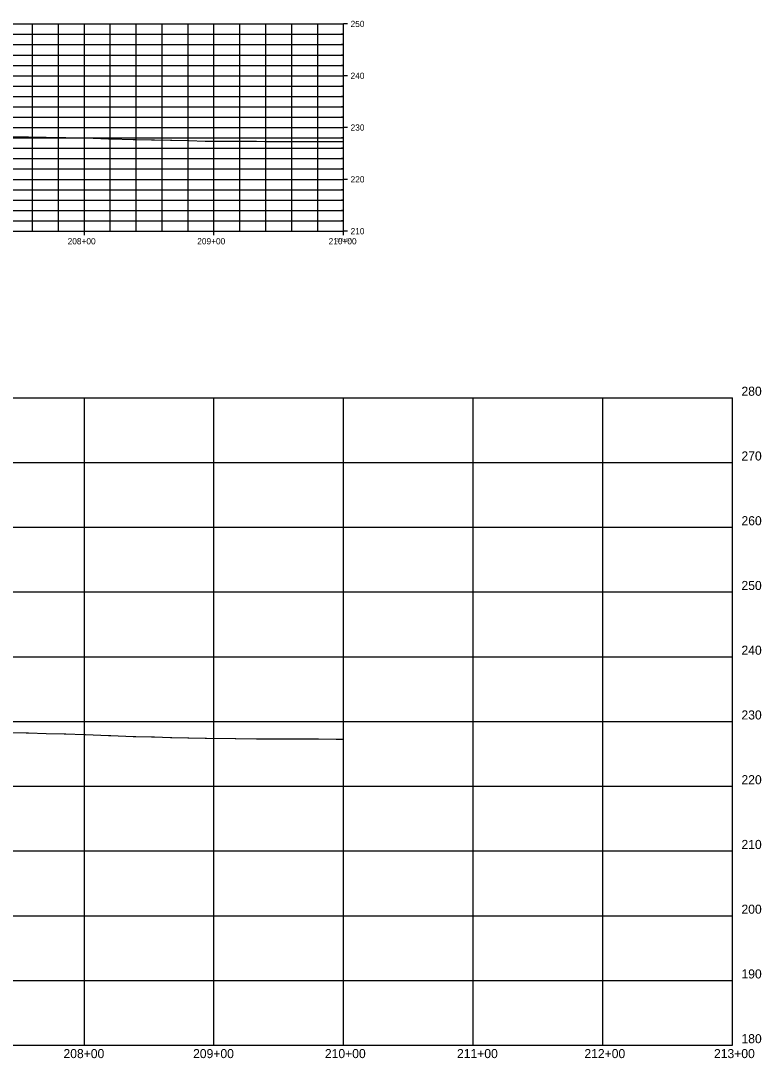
# Model space of a CAD drawing. Extents: x 1801553 to 1803097, y 521610 to 523048.
# Drawn here: x 1802526 to 1803097, y 521703 to 522504 of the extents above; entities that cross this region are included whole.
import ezdxf

# ---------------------------------------------------------------- set-up
doc = ezdxf.new("R2010")
doc.units = 0
for name, color, linetype in [('R_Axis', 7, 'Continuous'), ('R_Axis Annot', 7, 'Continuous'), ('R_Exist Surface', 7, 'Continuous'), ('R_Grid', 7, 'Continuous')]:
    doc.layers.add(name, color=color, linetype=linetype)

msp = doc.modelspace()

# ---------------------------------------------------------------- linework, layer by layer
at = {"layer": 'R_Axis'}
for p, q in [((1802774.68, 522341.48), (1802774.68, 522501.48)), ((1801774.68, 522341.48), (1802774.68, 522341.48)), ((1803074.68, 521712.85), (1803074.68, 522212.85)), ((1801574.68, 521712.85), (1803074.68, 521712.85))]:
    msp.add_line(p, q, dxfattribs=at)
at = {"layer": 'R_Exist Surface'}
for points in [[(1802516.38, 522414.65), (1802529.8, 522414.37), (1802531.51, 522414.33), (1802545.08, 522414.05), (1802558.97, 522413.76), (1802560.36, 522413.73), (1802574.41, 522413.44), (1802575.63, 522413.41), (1802593.19, 522412.86), (1802595.01, 522412.81), (1802612.32, 522412.27), (1802614.4, 522412.2), (1802626.58, 522411.94), (1802627.73, 522411.92), (1802628.88, 522411.9), (1802641.09, 522411.64), (1802642.05, 522411.63), (1802654.46, 522411.36), (1802655.23, 522411.35), (1802667.86, 522411.08), (1802668.94, 522411.07), (1802690.95, 522410.93), (1802691.41, 522410.93), (1802707.47, 522410.83), (1802713.84, 522410.78), (1802714, 522410.78), (1802727.69, 522410.74), (1802727.77, 522410.74), (1802741.46, 522410.69), (1802741.54, 522410.69), (1802755.24, 522410.65), (1802755.31, 522410.65), (1802755.38, 522410.65), (1802769.08, 522410.6), (1802769.14, 522410.6), (1802774.68, 522410.6)], [(1802516.38, 521954.32), (1802529.8, 521953.97), (1802531.51, 521953.92), (1802545.08, 521953.57), (1802558.97, 521953.21), (1802560.36, 521953.17), (1802574.41, 521952.8), (1802575.63, 521952.77), (1802593.19, 521952.08), (1802595.01, 521952.01), (1802612.32, 521951.34), (1802614.4, 521951.26), (1802626.58, 521950.93), (1802627.73, 521950.91), (1802628.88, 521950.88), (1802641.09, 521950.56), (1802642.05, 521950.54), (1802654.46, 521950.21), (1802655.23, 521950.19), (1802667.86, 521949.85), (1802668.94, 521949.84), (1802690.95, 521949.67), (1802691.41, 521949.67), (1802707.47, 521949.54), (1802713.84, 521949.48), (1802714, 521949.48), (1802727.69, 521949.43), (1802727.77, 521949.43), (1802741.46, 521949.37), (1802741.54, 521949.37), (1802755.24, 521949.31), (1802755.31, 521949.31), (1802755.38, 521949.31), (1802769.08, 521949.25), (1802769.14, 521949.25), (1802774.68, 521949.26)]]:
    msp.add_lwpolyline(points, dxfattribs=at)
at = {"layer": 'R_Grid'}
for p, q in [((1801774.68, 522501.48), (1802774.68, 522501.48)), ((1801774.68, 522501.48), (1802774.68, 522501.48)), ((1802534.68, 522341.48), (1802534.68, 522501.48)), ((1802554.68, 522341.48), (1802554.68, 522501.48)), ((1802574.68, 522341.48), (1802574.68, 522501.48)), ((1802594.68, 522341.48), (1802594.68, 522501.48)), ((1802614.68, 522341.48), (1802614.68, 522501.48)), ((1802634.68, 522341.48), (1802634.68, 522501.48)), ((1802654.68, 522341.48), (1802654.68, 522501.48)), ((1802674.68, 522341.48), (1802674.68, 522501.48)), ((1802694.68, 522341.48), (1802694.68, 522501.48)), ((1802714.68, 522341.48), (1802714.68, 522501.48)), ((1802734.68, 522341.48), (1802734.68, 522501.48)), ((1802754.68, 522341.48), (1802754.68, 522501.48)), ((1802777.68, 522501.48), (1802774.68, 522501.48)), ((1802777.68, 522501.48), (1802774.68, 522501.48)), ((1802774.68, 522341.48), (1802774.68, 522501.48)), ((1801774.68, 522493.48), (1802774.68, 522493.48)), ((1802774.68, 522493.48), (1802773.18, 522493.48)), ((1801774.68, 522485.48), (1802774.68, 522485.48)), ((1802774.68, 522485.48), (1802773.18, 522485.48)), ((1801774.68, 522477.48), (1802774.68, 522477.48)), ((1802774.68, 522477.48), (1802773.18, 522477.48)), ((1801774.68, 522469.48), (1802774.68, 522469.48)), ((1802774.68, 522469.48), (1802773.18, 522469.48)), ((1801774.68, 522461.48), (1802774.68, 522461.48)), ((1802777.68, 522461.48), (1802774.68, 522461.48)), ((1801774.68, 522453.48), (1802774.68, 522453.48)), ((1802774.68, 522453.48), (1802773.18, 522453.48)), ((1801774.68, 522445.48), (1802774.68, 522445.48)), ((1802774.68, 522445.48), (1802773.18, 522445.48)), ((1801774.68, 522437.48), (1802774.68, 522437.48)), ((1802774.68, 522437.48), (1802773.18, 522437.48)), ((1801774.68, 522429.48), (1802774.68, 522429.48)), ((1802774.68, 522429.48), (1802773.18, 522429.48)), ((1801774.68, 522421.48), (1802774.68, 522421.48)), ((1802777.68, 522421.48), (1802774.68, 522421.48)), ((1801774.68, 522413.48), (1802774.68, 522413.48)), ((1802774.68, 522413.48), (1802773.18, 522413.48)), ((1801774.68, 522405.48), (1802774.68, 522405.48)), ((1802774.68, 522405.48), (1802773.18, 522405.48)), ((1801774.68, 522397.48), (1802774.68, 522397.48)), ((1802774.68, 522397.48), (1802773.18, 522397.48)), ((1801774.68, 522389.48), (1802774.68, 522389.48)), ((1802774.68, 522389.48), (1802773.18, 522389.48)), ((1801774.68, 522381.48), (1802774.68, 522381.48)), ((1802777.68, 522381.48), (1802774.68, 522381.48)), ((1801774.68, 522373.48), (1802774.68, 522373.48)), ((1802774.68, 522373.48), (1802773.18, 522373.48)), ((1801774.68, 522365.48), (1802774.68, 522365.48)), ((1802774.68, 522365.48), (1802773.18, 522365.48)), ((1801774.68, 522357.48), (1802774.68, 522357.48)), ((1802774.68, 522357.48), (1802773.18, 522357.48)), ((1801774.68, 522349.48), (1802774.68, 522349.48)), ((1802774.68, 522349.48), (1802773.18, 522349.48)), ((1802574.68, 522338.48), (1802574.68, 522341.48)), ((1802674.68, 522338.48), (1802674.68, 522341.48)), ((1802777.68, 522341.48), (1802774.68, 522341.48)), ((1802774.68, 522338.48), (1802774.68, 522341.48)), ((1802774.68, 522338.48), (1802774.68, 522341.48)), ((1801574.68, 522212.85), (1803074.68, 522212.85)), ((1802574.68, 521712.85), (1802574.68, 522212.85)), ((1802674.68, 521712.85), (1802674.68, 522212.85)), ((1802774.68, 521712.85), (1802774.68, 522212.85)), ((1802874.68, 521712.85), (1802874.68, 522212.85)), ((1802974.68, 521712.85), (1802974.68, 522212.85)), ((1801574.68, 522162.85), (1803074.68, 522162.85)), ((1801574.68, 522112.85), (1803074.68, 522112.85)), ((1801574.68, 522112.85), (1803074.68, 522112.85)), ((1801574.68, 522062.85), (1803074.68, 522062.85)), ((1801574.68, 522012.85), (1803074.68, 522012.85)), ((1801574.68, 521962.85), (1803074.68, 521962.85)), ((1801574.68, 521912.85), (1803074.68, 521912.85)), ((1801574.68, 521862.85), (1803074.68, 521862.85)), ((1801574.68, 521812.85), (1803074.68, 521812.85)), ((1801574.68, 521762.85), (1803074.68, 521762.85))]:
    msp.add_line(p, q, dxfattribs=at)

# ---------------------------------------------------------------- texts
at = {"layer": 'R_Axis Annot'}
for s, height, p in [('250', 4.8, (1802780.08, 522499.08)), ('240', 4.8, (1802780.08, 522459.08)), ('230', 4.8, (1802780.08, 522419.08)), ('220', 4.8, (1802780.08, 522379.08)), ('210', 4.8, (1802780.08, 522339.08)), ('208+00', 4.8, (1802561.77, 522331.28)), ('209+00', 4.8, (1802661.77, 522331.28)), ('210+00', 4.8, (1802763.13, 522331.28)), ('210+00', 2.4, (1802768.91, 522333.68)), ('280', 7, (1803081.68, 522214.35)), ('270', 7, (1803081.68, 522164.35)), ('260', 7, (1803081.68, 522114.35)), ('260', 7, (1803081.68, 522114.35)), ('250', 7, (1803081.68, 522064.35)), ('240', 7, (1803081.68, 522014.35)), ('230', 7, (1803081.68, 521964.35)), ('220', 7, (1803081.68, 521914.35)), ('210', 7, (1803081.68, 521864.35)), ('200', 7, (1803081.68, 521814.35)), ('190', 7, (1803081.68, 521764.35)), ('180', 7, (1803081.68, 521714.35)), ('208+00', 7, (1802558.55, 521702.85)), ('209+00', 7, (1802658.55, 521702.85)), ('210+00', 7, (1802760.25, 521702.85)), ('211+00', 7, (1802862.18, 521702.85)), ('212+00', 7, (1802960.48, 521702.85)), ('213+00', 7, (1803060.48, 521702.85))]:
    msp.add_text(s, height=height, dxfattribs=at).set_placement(p)

doc.saveas('drawing.dxf')
